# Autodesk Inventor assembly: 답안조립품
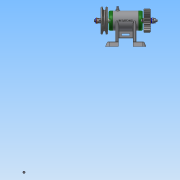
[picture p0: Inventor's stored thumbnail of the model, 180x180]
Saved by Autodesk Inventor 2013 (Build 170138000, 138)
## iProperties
Created: 2016-07
Part Number: 답안조립품
Document SubType Name: Assembly
Designer: Administrator
Author: Administrator
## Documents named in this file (16)
- C:\Users\Administrator\Desktop\460708V1019\답안조립품.iam
- C:\Users\Administrator\Desktop\460708V1019\본체.ipt
- C:\Users\Administrator\Desktop\460708V1019\V벨트풀리.ipt
- C:\Users\Administrator\Desktop\460708V1019\너트 M 8.ipt
- C:\Users\Administrator\Desktop\460708V1019\니플 M 6 x 0.75.ipt
- C:\Users\Administrator\Desktop\460708V1019\베어링 15 x 32 x 9.ipt
- C:\Users\Administrator\Desktop\460708V1019\볼트 M 6 x 8.ipt
- C:\Users\Administrator\Desktop\460708V1019\볼트 M4 x 12.ipt
- C:\Users\Administrator\Desktop\460708V1019\스퍼기어.ipt
- C:\Users\Administrator\Desktop\460708V1019\스프링와셔 8.ipt
- C:\Users\Administrator\Desktop\460708V1019\오일 실 15 25 7.ipt
- C:\Users\Administrator\Desktop\460708V1019\와셔 6x11.5.ipt
- C:\Users\Administrator\Desktop\460708V1019\와셔 8x17.ipt
- C:\Users\Administrator\Desktop\460708V1019\축.ipt
- C:\Users\Administrator\Desktop\460708V1019\커버.ipt
- C:\Users\Administrator\Desktop\460708V1019\키 3 x 3 x 12.ipt
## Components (12 placed, 3 different names)
1. V벨트풀리:1
2. KS B 2023 6002 - 15 x 32 x 9:1
3. KS B 2023 6002 - 15 x 32 x 9:2
4. ISO 4762 M4 x 12:9
5. ISO 4762 M4 x 12:2
6. ISO 4762 M4 x 12:3
7. ISO 4762 M4 x 12:4
8. ISO 4762 M4 x 12:5
9. ISO 4762 M4 x 12:1
10. ISO 4762 M4 x 12:6
11. ISO 4762 M4 x 12:7
12. ISO 4762 M4 x 12:8
